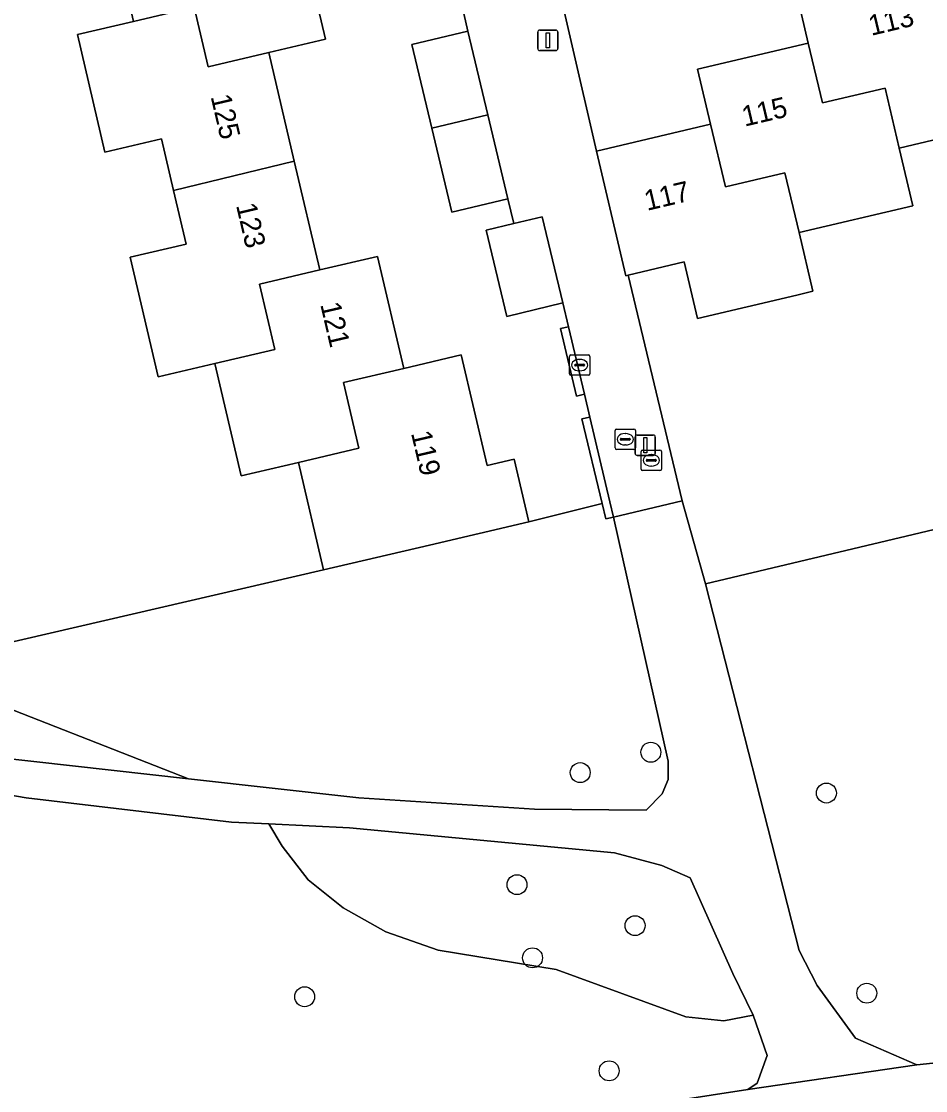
# Model space of a CAD drawing. Extents: x 158031 to 159244, y 380104 to 381214.
# Drawn here: x 158849.9 to 158894.3, y 380406.3 to 380458.7 of the extents above; entities that cross this region are included whole.
import ezdxf

# ---------------------------------------------------------------- set-up
doc = ezdxf.new("R2010")
doc.units = 0
for name, color, linetype in [('IMGEO_Boom', 7, 'Continuous'), ('IMGEO_Brandkraan', 7, 'Continuous'), ('IMGEO_Erf', 7, 'Continuous'), ('IMGEO_Groenvoorziening', 7, 'Continuous'), ('IMGEO_Haag', 7, 'Continuous'), ('IMGEO_Hek', 7, 'Continuous'), ('IMGEO_Kolk', 7, 'Continuous'), ('IMGEO_Lichtmast', 7, 'Continuous'), ('IMGEO_Pand', 7, 'Continuous'), ('IMGEO_Pand_nummerreeks', 7, 'Continuous'), ('IMGEO_Rioolput', 7, 'Continuous'), ('IMGEO_Voetpad_halfverhard', 7, 'Continuous'), ('IMGEO_Voetpad_open', 7, 'Continuous')]:
    doc.layers.add(name, color=color, linetype=linetype)

msp = doc.modelspace()

# ---------------------------------------------------------------- linework, layer by layer
at = {"layer": 'IMGEO_Boom'}
for centre in [(158880.784, 380422.883), (158877.317, 380421.884), (158889.399, 380420.883), (158874.214, 380416.388), (158880.009, 380414.379), (158874.978, 380412.801), (158891.379, 380411.065), (158863.793, 380410.892), (158878.734, 380407.257)]:
    msp.add_circle(centre, 0.489, dxfattribs=at)
at = {"layer": 'IMGEO_Brandkraan'}
for p, q in [((158879.103, 380438.734), (158879.955, 380438.734)), ((158879.028, 380437.808), (158879.028, 380438.66)), ((158879.287, 380438.228), (158879.287, 380438.24)), ((158879.725, 380438.191), (158879.327, 380438.191)), ((158879.33, 380438.277), (158879.728, 380438.277)), ((158879.516, 380438.514), (158879.541, 380438.514)), ((158879.771, 380438.24), (158879.771, 380438.228)), ((158880.029, 380438.66), (158880.029, 380437.808)), ((158879.955, 380437.734), (158879.103, 380437.734)), ((158879.539, 380437.954), (158879.514, 380437.954))]:
    msp.add_line(p, q, dxfattribs=at)
for points in [[(158879.103, 380438.734), (158879.955, 380438.734)], [(158879.028, 380437.808), (158879.028, 380438.66)], [(158880.029, 380438.66), (158880.029, 380437.808)], [(158879.955, 380437.734), (158879.103, 380437.734)]]:
    msp.add_lwpolyline(points, dxfattribs=at)
for centre, radius, start, end in [((158879.105, 380438.658), 0.0765, 91.552, 178.448), ((158879.105, 380438.658), 0.0765, 91.552, 178.448), ((158879.953, 380438.658), 0.0765, 1.552, 88.448), ((158879.953, 380438.658), 0.0765, 1.552, 88.448), ((158879.327, 380438.237), 0.0403, 85.8775, 175.7526), ((158879.324, 380438.227), 0.0366, 178.938, 274.7102), ((158879.728, 380438.234), 0.043, 264.8664, 352.4533), ((158879.732, 380438.239), 0.0386, 1.7309, 96.639), ((158879.105, 380437.81), 0.0765, 181.552, 268.448), ((158879.105, 380437.81), 0.0765, 181.552, 268.448), ((158879.953, 380437.81), 0.0765, 271.552, 358.448), ((158879.953, 380437.81), 0.0765, 271.552, 358.448)]:
    msp.add_arc(centre, radius, start, end, dxfattribs=at)
for centre, major_axis, ratio, start_param, end_param in [((158879.515, 380438.234), (-0.387, 0.002), 0.722429, 4.712389, 7.853982), ((158879.54, 380438.234), (-0.39, 0.002), 0.717154, 1.570796, 4.712389)]:
    msp.add_ellipse(centre, major_axis=major_axis, ratio=ratio, start_param=start_param, end_param=end_param, dxfattribs=at)
at = {"layer": 'IMGEO_Erf'}
for points in [[(158847.26, 380427.799), (158864.723, 380431.826), (158863.491, 380437.098), (158860.674, 380436.439), (158859.388, 380441.942), (158856.609, 380441.292), (158855.237, 380447.165), (158857.972, 380447.805), (158857.357, 380450.438), (158856.767, 380452.962), (158853.987, 380452.312), (158852.638, 380458.083), (158855.397, 380458.728), (158854.127, 380464.167), (158856.967, 380464.831), (158855.692, 380470.289), (158854.473, 380475.506), (158851.602, 380474.835), (158850.32, 380480.32), (158847.275, 380479.609)], [(158898.691, 380471.478), (158889.887, 380469.384), (158889.831, 380469.617), (158884.623, 380468.402), (158885.271, 380465.668), (158881.03, 380464.662), (158880.382, 380467.396), (158879.161, 380467.096), (158879.809, 380464.362), (158875.573, 380463.354), (158878.114, 380452.364), (158883.716, 380453.688), (158883.08, 380456.39), (158888.508, 380457.669), (158887.842, 380460.495), (158893.328, 380461.788), (158893.027, 380463.064), (158895.908, 380463.743)], [(158863.53, 380463.329), (158864.811, 380457.85), (158862.039, 380457.202), (158863.285, 380451.868), (158864.531, 380446.537), (158867.373, 380447.201), (158868.657, 380441.708), (158871.482, 380442.369), (158872.748, 380436.949), (158874.073, 380437.259), (158874.792, 380434.179), (158878.387, 380435.081), (158877.401, 380439.234), (158877.79, 380439.326), (158877.524, 380440.445), (158877.135, 380440.353), (158876.349, 380443.661), (158876.738, 380443.753), (158876.461, 380444.921), (158873.709, 380444.261), (158872.693, 380448.495), (158874.051, 380448.818), (158873.762, 380450.034), (158871.008, 380449.38), (158870.031, 380453.49), (158869.053, 380457.6), (158871.806, 380458.255), (158871.515, 380459.481)], [(158898.266, 380453.764), (158892.97, 380452.516), (158893.637, 380449.686), (158888.054, 380448.37), (158888.732, 380445.492), (158887.942, 380445.306), (158883.075, 380444.16), (158882.422, 380446.931), (158879.673, 380446.281), (158882.321, 380435.221), (158883.466, 380431.148), (158973.949, 380452.625)]]:
    msp.add_lwpolyline(points, dxfattribs=at)
at = {"layer": 'IMGEO_Groenvoorziening'}
for points in [[(159006.925, 380451.21), (159005.828, 380456.746), (159004.857, 380456.513), (159005.809, 380452.471), (159000.386, 380451.105), (158975.667, 380445.423), (158973.949, 380452.625), (158883.466, 380431.148), (158888.059, 380413.158), (158888.945, 380411.442), (158890.833, 380408.861), (158893.84, 380407.549), (158904.192, 380408.639), (158913.221, 380409.146), (158921.261, 380409.922), (158925.707, 380410.919), (158927.74, 380411.665), (158930.409, 380413.109), (158934.592, 380416.844), (158944.855, 380424.497)], [(158807.12, 380428.681), (158812.148, 380428.444), (158819.754, 380427.457), (158838.716, 380424.226), (158848.581, 380422.637), (158858.09, 380421.576), (158846.643, 380426.065), (158847.26, 380427.799), (158842.551, 380448.184)], [(158829.205, 380393.026), (158851.947, 380400.142), (158858.033, 380401.632), (158867.331, 380403.524), (158885.546, 380406.342), (158886.004, 380406.646), (158886.488, 380408.004), (158885.812, 380409.989), (158884.369, 380409.714), (158882.503, 380409.907), (158876.133, 380412.225), (158870.346, 380413.171), (158867.782, 380414.075), (158865.676, 380415.246), (158863.964, 380416.619), (158862.694, 380418.278), (158862.028, 380419.365), (158860.195, 380419.453), (158850.121, 380420.641), (158835.96, 380423.102)]]:
    msp.add_lwpolyline(points, dxfattribs=at)
for points in [[(158876.738, 380443.753), (158876.349, 380443.661), (158877.135, 380440.353), (158877.524, 380440.445)], [(158877.79, 380439.326), (158877.401, 380439.234), (158878.387, 380435.081), (158878.566, 380434.327), (158878.955, 380434.42), (158878.776, 380435.173)], [(158878.955, 380434.42), (158878.566, 380434.327), (158878.387, 380435.081), (158874.792, 380434.179), (158869.924, 380433.041), (158864.723, 380431.826), (158847.26, 380427.799), (158846.643, 380426.065), (158858.09, 380421.576), (158866.445, 380420.643), (158875.079, 380420.097), (158880.552, 380420.039), (158881.341, 380420.85), (158881.634, 380421.548), (158881.635, 380422.45)], [(158862.028, 380419.365), (158862.694, 380418.278), (158863.964, 380416.619), (158865.676, 380415.246), (158867.782, 380414.075), (158870.346, 380413.171), (158876.133, 380412.225), (158882.503, 380409.907), (158884.369, 380409.714), (158885.812, 380409.989), (158884.806, 380412.032), (158882.719, 380416.724), (158881.319, 380417.336), (158879.002, 380417.948), (158866.001, 380419.174)]]:
    msp.add_lwpolyline(points, close=True, dxfattribs=at)
at = {"layer": 'IMGEO_Haag'}
for points in [[(158876.738, 380443.753), (158876.349, 380443.661), (158877.135, 380440.353), (158877.524, 380440.445)], [(158877.79, 380439.326), (158877.401, 380439.234), (158878.387, 380435.081), (158878.566, 380434.327), (158878.955, 380434.42), (158878.776, 380435.173)]]:
    msp.add_lwpolyline(points, close=True, dxfattribs=at)
at = {"layer": 'IMGEO_Hek'}
for points in [[(158882.321, 380435.221), (158879.673, 380446.281)], [(158883.466, 380431.148), (158882.321, 380435.221)]]:
    msp.add_lwpolyline(points, dxfattribs=at)
at = {"layer": 'IMGEO_Kolk'}
for p, q in [((158876.863, 380442.371), (158877.715, 380442.371)), ((158876.788, 380441.445), (158876.788, 380442.297)), ((158877.047, 380441.865), (158877.047, 380441.877)), ((158877.485, 380441.828), (158877.087, 380441.828)), ((158877.09, 380441.914), (158877.488, 380441.914)), ((158877.276, 380442.151), (158877.301, 380442.151)), ((158877.531, 380441.877), (158877.531, 380441.865)), ((158877.789, 380442.297), (158877.789, 380441.445)), ((158877.715, 380441.371), (158876.863, 380441.371)), ((158877.299, 380441.591), (158877.274, 380441.591))]:
    msp.add_line(p, q, dxfattribs=at)
for points in [[(158876.863, 380442.371), (158877.715, 380442.371)], [(158876.788, 380441.445), (158876.788, 380442.297)], [(158877.789, 380442.297), (158877.789, 380441.445)], [(158877.715, 380441.371), (158876.863, 380441.371)]]:
    msp.add_lwpolyline(points, dxfattribs=at)
for centre, radius, start, end in [((158876.865, 380442.295), 0.0765, 91.552, 178.448), ((158876.865, 380442.295), 0.0765, 91.552, 178.448), ((158877.713, 380442.295), 0.0765, 1.552, 88.448), ((158877.713, 380442.295), 0.0765, 1.552, 88.448), ((158877.087, 380441.874), 0.0403, 85.8775, 175.7526), ((158877.084, 380441.864), 0.0366, 178.938, 274.7102), ((158877.488, 380441.871), 0.043, 264.8664, 352.4533), ((158877.492, 380441.876), 0.0386, 1.7309, 96.639), ((158876.865, 380441.447), 0.0765, 181.552, 268.448), ((158876.865, 380441.447), 0.0765, 181.552, 268.448), ((158877.713, 380441.447), 0.0765, 271.552, 358.448), ((158877.713, 380441.447), 0.0765, 271.552, 358.448)]:
    msp.add_arc(centre, radius, start, end, dxfattribs=at)
for centre, major_axis, ratio, start_param, end_param in [((158877.275, 380441.871), (-0.387, 0.002), 0.722429, 4.712389, 7.853982), ((158877.3, 380441.871), (-0.39, 0.002), 0.717154, 1.570796, 4.712389)]:
    msp.add_ellipse(centre, major_axis=major_axis, ratio=ratio, start_param=start_param, end_param=end_param, dxfattribs=at)
at = {"layer": 'IMGEO_Lichtmast'}
for p, q in [((158875.231, 380457.401), (158875.231, 380458.201)), ((158875.231, 380458.201), (158875.231, 380457.401)), ((158875.331, 380458.301), (158876.121, 380458.301)), ((158876.121, 380458.301), (158875.331, 380458.301)), ((158876.221, 380458.201), (158876.221, 380457.401)), ((158876.221, 380457.401), (158876.221, 380458.201)), ((158876.121, 380457.301), (158875.331, 380457.301)), ((158875.331, 380457.301), (158876.121, 380457.301)), ((158880.012, 380437.54), (158880.012, 380438.34)), ((158880.012, 380438.34), (158880.012, 380437.54)), ((158880.112, 380438.44), (158880.902, 380438.44)), ((158880.902, 380438.44), (158880.112, 380438.44)), ((158881.002, 380438.34), (158881.002, 380437.54)), ((158881.002, 380437.54), (158881.002, 380438.34)), ((158880.902, 380437.44), (158880.112, 380437.44)), ((158880.112, 380437.44), (158880.902, 380437.44))]:
    msp.add_line(p, q, dxfattribs=at)
for points in [[(158875.651, 380458.176), (158875.801, 380458.176), (158875.801, 380457.426), (158875.651, 380457.426), (158875.651, 380458.176)], [(158880.432, 380438.315), (158880.582, 380438.315), (158880.582, 380437.565), (158880.432, 380437.565), (158880.432, 380438.315)]]:
    msp.add_lwpolyline(points, dxfattribs=at)
for centre, start, end in [((158875.331, 380458.201), 90, 180), ((158875.331, 380458.201), 90, 180), ((158876.121, 380458.201), 0, 90), ((158876.121, 380458.201), 360, 90), ((158875.331, 380457.401), 180, 270), ((158875.331, 380457.401), 180, 270), ((158876.121, 380457.401), 270, 0), ((158876.121, 380457.401), 270, 0), ((158880.112, 380438.34), 90, 180), ((158880.112, 380438.34), 90, 180), ((158880.902, 380438.34), 0, 90), ((158880.902, 380438.34), 360, 90), ((158880.112, 380437.54), 180, 270), ((158880.112, 380437.54), 180, 270), ((158880.902, 380437.54), 270, 0), ((158880.902, 380437.54), 270, 0)]:
    msp.add_arc(centre, 0.1, start, end, dxfattribs=at)
at = {"layer": 'IMGEO_Pand'}
for points in [[(158855.397, 380458.728), (158858.377, 380459.425), (158859.059, 380456.505), (158862.039, 380457.202), (158864.811, 380457.85), (158863.53, 380463.329), (158860.585, 380462.641), (158859.912, 380465.52), (158856.967, 380464.831), (158854.127, 380464.167)], [(158898.266, 380453.764), (158895.908, 380463.743), (158893.027, 380463.064), (158893.328, 380461.788), (158887.842, 380460.495), (158888.508, 380457.669), (158889.201, 380454.73), (158892.277, 380455.455), (158892.97, 380452.516)], [(158855.397, 380458.728), (158852.638, 380458.083), (158853.987, 380452.312), (158856.767, 380452.962), (158857.357, 380450.438), (158863.285, 380451.868), (158862.039, 380457.202), (158859.059, 380456.505), (158858.377, 380459.425)], [(158872.784, 380454.145), (158871.806, 380458.255), (158869.053, 380457.6), (158870.031, 380453.49)], [(158883.716, 380453.688), (158884.439, 380450.615), (158887.363, 380451.303), (158888.054, 380448.37), (158893.637, 380449.686), (158892.97, 380452.516), (158892.277, 380455.455), (158889.201, 380454.73), (158888.508, 380457.669), (158883.08, 380456.39)], [(158872.784, 380454.145), (158870.031, 380453.49), (158871.008, 380449.38), (158873.762, 380450.034)], [(158883.716, 380453.688), (158878.114, 380452.364), (158879.559, 380446.254), (158879.673, 380446.281), (158882.422, 380446.931), (158883.075, 380444.16), (158887.942, 380445.306), (158888.732, 380445.492), (158888.054, 380448.37), (158887.363, 380451.303), (158884.439, 380450.615)], [(158863.285, 380451.868), (158857.357, 380450.438), (158857.972, 380447.805), (158855.237, 380447.165), (158856.609, 380441.292), (158859.388, 380441.942), (158862.336, 380442.631), (158861.584, 380445.848), (158864.531, 380446.537)], [(158874.051, 380448.818), (158872.693, 380448.495), (158873.709, 380444.261), (158876.461, 380444.921), (158875.446, 380449.15)], [(158868.657, 380441.708), (158867.373, 380447.201), (158864.531, 380446.537), (158861.584, 380445.848), (158862.336, 380442.631), (158859.388, 380441.942), (158860.674, 380436.439), (158863.491, 380437.098), (158866.451, 380437.791), (158865.697, 380441.015)], [(158868.657, 380441.708), (158865.697, 380441.015), (158866.451, 380437.791), (158863.491, 380437.098), (158864.723, 380431.826), (158869.924, 380433.041), (158874.792, 380434.179), (158874.073, 380437.259), (158872.748, 380436.949), (158871.482, 380442.369)]]:
    msp.add_lwpolyline(points, close=True, dxfattribs=at)
at = {"layer": 'IMGEO_Rioolput'}
for p, q in [((158880.304, 380436.775), (158880.304, 380437.627)), ((158880.379, 380437.701), (158881.231, 380437.701)), ((158881.305, 380437.627), (158881.305, 380436.775)), ((158880.563, 380437.195), (158880.563, 380437.207)), ((158881.001, 380437.158), (158880.603, 380437.158)), ((158880.606, 380437.244), (158881.004, 380437.244)), ((158880.792, 380437.481), (158880.817, 380437.481)), ((158881.047, 380437.207), (158881.047, 380437.195)), ((158881.231, 380436.701), (158880.379, 380436.701)), ((158880.815, 380436.921), (158880.79, 380436.921))]:
    msp.add_line(p, q, dxfattribs=at)
for points in [[(158880.304, 380436.775), (158880.304, 380437.627)], [(158880.379, 380437.701), (158881.231, 380437.701)], [(158881.305, 380437.627), (158881.305, 380436.775)], [(158881.231, 380436.701), (158880.379, 380436.701)]]:
    msp.add_lwpolyline(points, dxfattribs=at)
for centre, radius, start, end in [((158880.381, 380437.625), 0.0765, 91.552, 178.448), ((158880.381, 380437.625), 0.0765, 91.552, 178.448), ((158881.229, 380437.625), 0.0765, 1.552, 88.448), ((158881.229, 380437.625), 0.0765, 1.552, 88.448), ((158880.603, 380437.204), 0.0403, 85.8775, 175.7526), ((158880.6, 380437.194), 0.0366, 178.938, 274.7102), ((158881.004, 380437.201), 0.043, 264.8664, 352.4533), ((158881.008, 380437.206), 0.0386, 1.7309, 96.639), ((158880.381, 380436.777), 0.0765, 181.552, 268.448), ((158880.381, 380436.777), 0.0765, 181.552, 268.448), ((158881.229, 380436.777), 0.0765, 271.552, 358.448), ((158881.229, 380436.777), 0.0765, 271.552, 358.448)]:
    msp.add_arc(centre, radius, start, end, dxfattribs=at)
for centre, major_axis, ratio, start_param, end_param in [((158880.791, 380437.201), (-0.387, 0.002), 0.722429, 4.712389, 7.853982), ((158880.816, 380437.201), (-0.39, 0.002), 0.717154, 1.570796, 4.712389)]:
    msp.add_ellipse(centre, major_axis=major_axis, ratio=ratio, start_param=start_param, end_param=end_param, dxfattribs=at)
at = {"layer": 'IMGEO_Voetpad_halfverhard'}
for points in [[(158835.96, 380423.102), (158850.121, 380420.641), (158860.195, 380419.453), (158862.028, 380419.365), (158866.001, 380419.174), (158879.002, 380417.948), (158881.319, 380417.336), (158882.719, 380416.724), (158884.806, 380412.032), (158885.812, 380409.989), (158886.488, 380408.004), (158886.004, 380406.646), (158885.546, 380406.342), (158893.84, 380407.549), (158890.833, 380408.861), (158888.945, 380411.442), (158888.059, 380413.158), (158883.466, 380431.148), (158882.321, 380435.221), (158878.955, 380434.42), (158881.635, 380422.45), (158881.634, 380421.548), (158881.341, 380420.85), (158880.552, 380420.039), (158875.079, 380420.097), (158866.445, 380420.643), (158858.09, 380421.576), (158848.581, 380422.637)], [(158931.468, 380405.396), (158928.059, 380407.537), (158921.261, 380409.922), (158913.221, 380409.146), (158904.192, 380408.639), (158893.84, 380407.549), (158885.546, 380406.342), (158867.331, 380403.524)]]:
    msp.add_lwpolyline(points, dxfattribs=at)
at = {"layer": 'IMGEO_Voetpad_open'}
msp.add_lwpolyline([(158875.573, 380463.354), (158874.934, 380466.094), (158871.61, 380465.306), (158871.907, 380464.055), (158872.916, 380459.814), (158871.515, 380459.481), (158871.806, 380458.255), (158872.784, 380454.145), (158873.762, 380450.034), (158874.051, 380448.818), (158875.446, 380449.15), (158876.461, 380444.921), (158876.738, 380443.753), (158877.524, 380440.445), (158877.79, 380439.326), (158878.776, 380435.173), (158878.955, 380434.42), (158882.321, 380435.221), (158879.673, 380446.281), (158879.559, 380446.254), (158878.114, 380452.364)], close=True, dxfattribs=at)

# ---------------------------------------------------------------- texts
at = {"layer": 'IMGEO_Pand_nummerreeks'}
for s, rotation, p in [('113', 13.4074, (158891.599, 380458.019)), ('125', 283.1519, (158859.175, 380455.043)), ('115', 13.2588, (158885.383, 380453.563)), ('117', 13.2626, (158880.593, 380449.434)), ('123', 283.1519, (158860.421, 380449.71)), ('121', 283.1568, (158864.554, 380444.85)), ('119', 283.1474, (158869.009, 380438.537))]:
    msp.add_text(s, height=1, rotation=rotation, dxfattribs=at).set_placement(p)

doc.saveas('drawing.dxf')
